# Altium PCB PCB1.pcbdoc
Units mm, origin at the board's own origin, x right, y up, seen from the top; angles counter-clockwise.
Board outline 70.36 x 65.79 mm, 2 copper layers (Top Layer, Bottom Layer), stack 1.58 mm thick; 58 components, 70 nets, 284 pads, 61 vias.
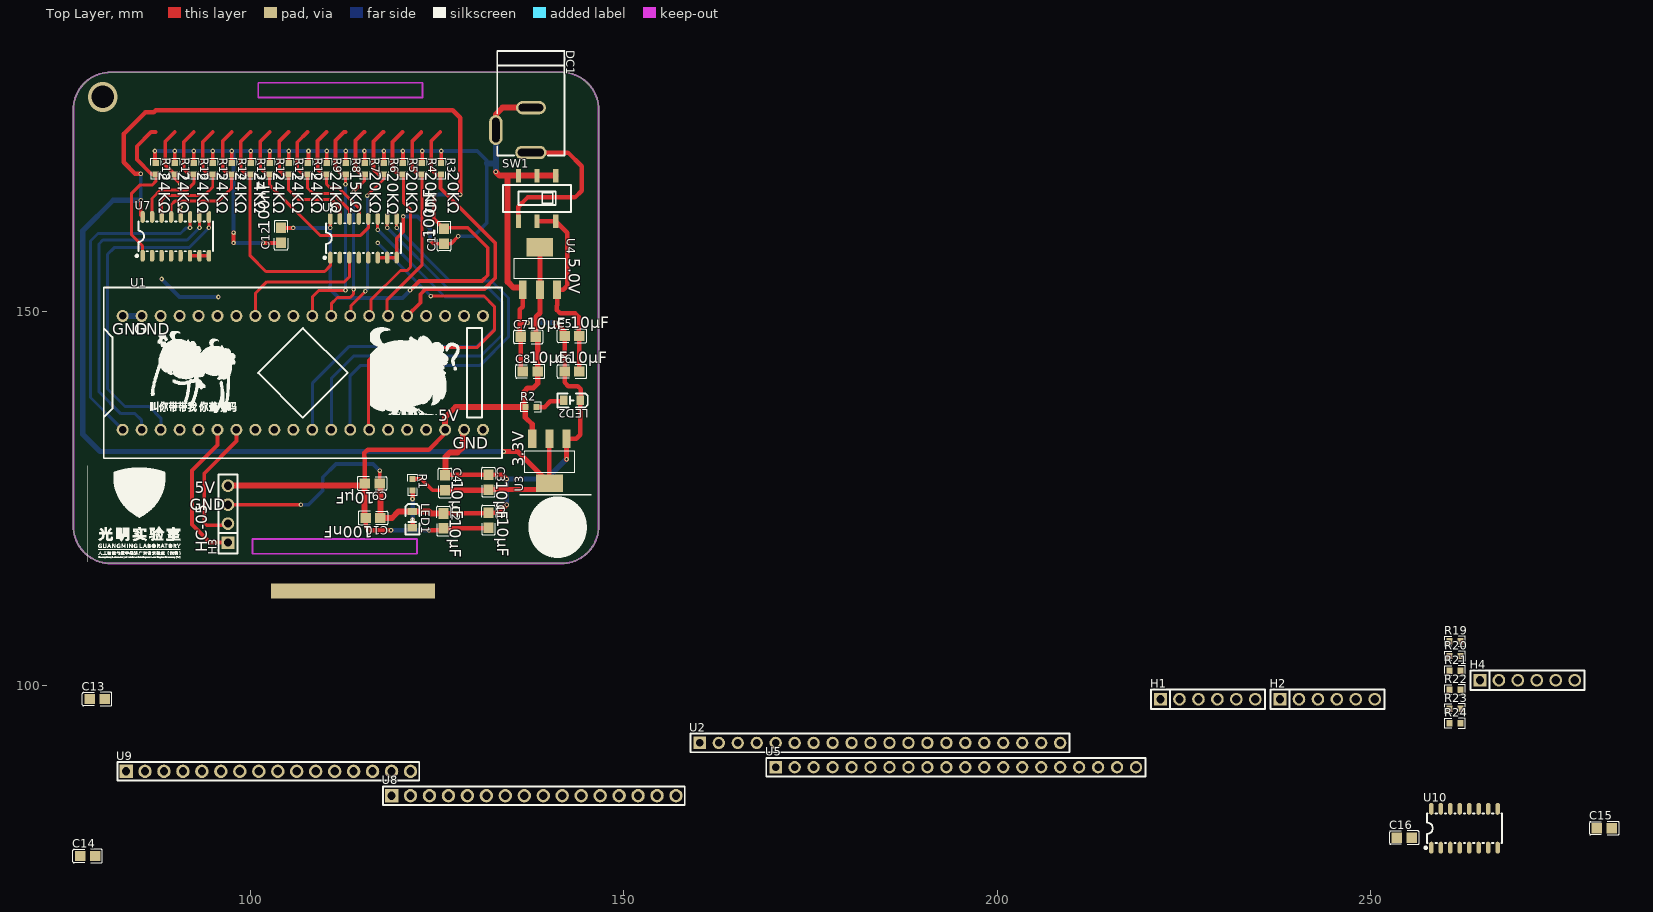
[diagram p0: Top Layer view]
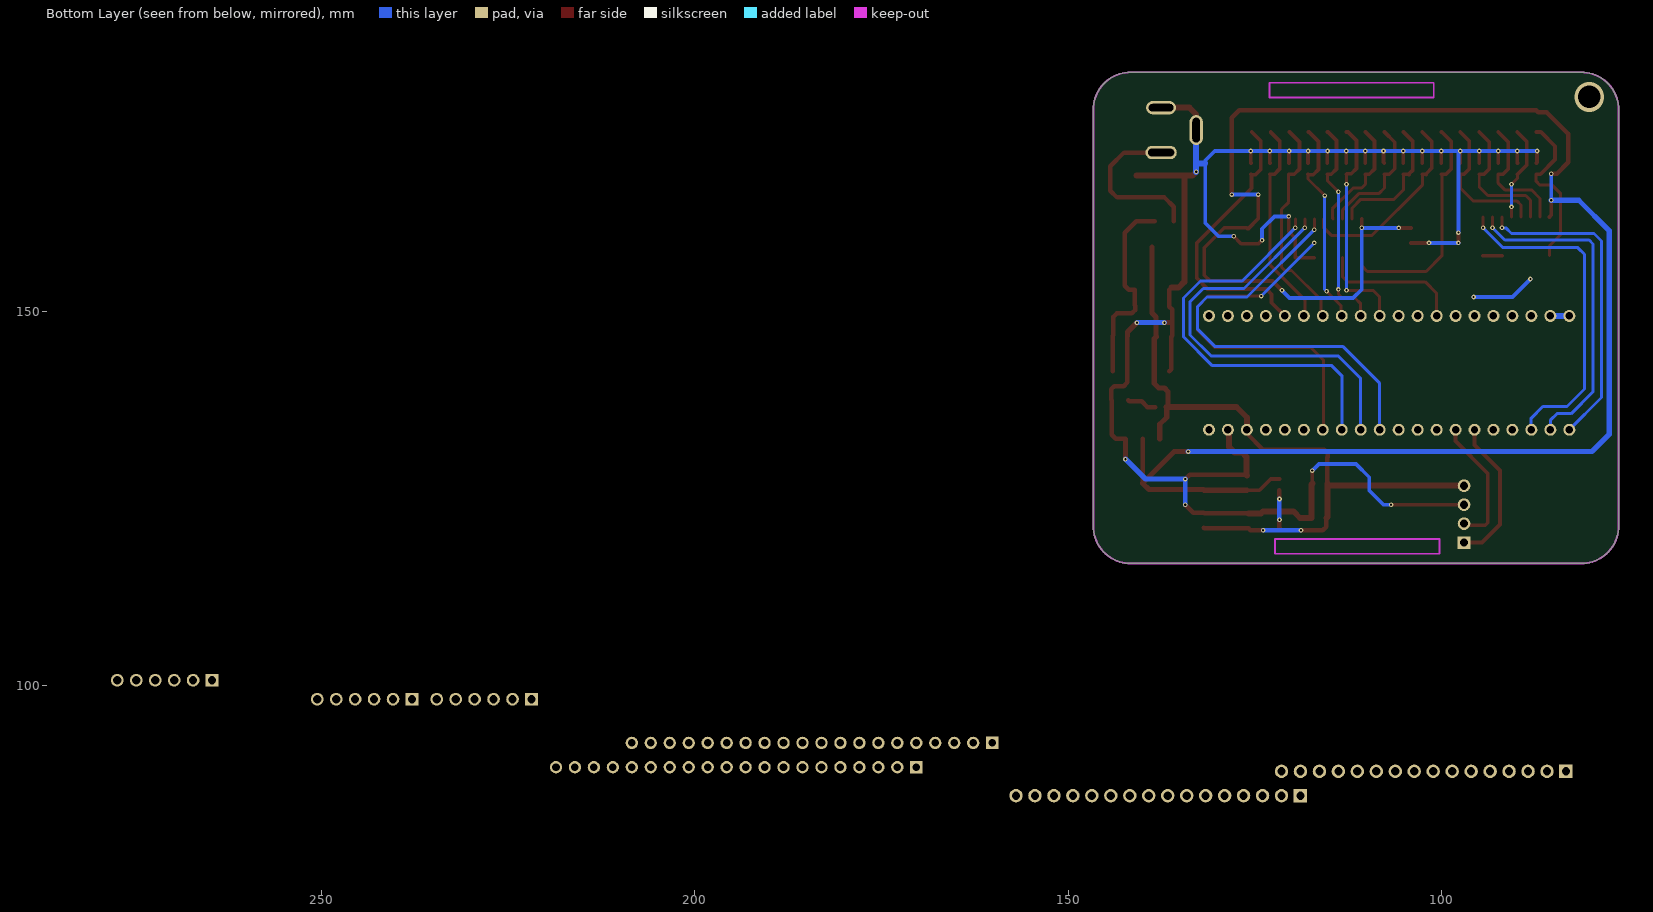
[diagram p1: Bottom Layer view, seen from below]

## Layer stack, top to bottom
Top Solder Mask Layer: solder mask 0.01, Dk 3.3
Top Layer: signal copper 0.035
Dielectric1: surface 1.51, FR4, Dk 4.5
Bottom Layer: signal copper 0.035
Bottom Solder Mask Layer: solder mask 0.01, Dk 3.3

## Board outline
81.251,182.084 ccw(c81.251,177.084) 76.251,177.084 76.251,121.298 ccw(c81.251,121.298) 81.251,116.298 141.609,116.298 ccw(c141.609,121.298) 146.609,121.298 146.609,177.084 ccw(c141.609,177.084) 141.609,182.084

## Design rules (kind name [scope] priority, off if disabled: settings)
BoardOutlineClearance copperThickness1oz [All] p0: genericclearance=0.254 ignorepadtopadclearanceinfootprint=FALSE except(0: Arc-SplitContinuation Track-SplitContinuation SMDPad-SplitContinuation THPad-SplitContinuation Via-SplitContinuation Fill-SplitContinuation Poly-SplitContinuation Region-SplitContinuation Text-SplitContinuation)
BoardOutlineClearance copperThickness2oz [All] p0: genericclearance=0.254 ignorepadtopadclearanceinfootprint=FALSE except(0: Arc-SplitContinuation Track-SplitContinuation SMDPad-SplitContinuation THPad-SplitContinuation Via-SplitContinuation Fill-SplitContinuation Poly-SplitContinuation Region-SplitContinuation Text-SplitContinuation)
BoardOutlineClearance Plane_innerPlane [All] p0: genericclearance=0.254 ignorepadtopadclearanceinfootprint=FALSE except(0: Arc-SplitContinuation Track-SplitContinuation SMDPad-SplitContinuation THPad-SplitContinuation Via-SplitContinuation Fill-SplitContinuation Poly-SplitContinuation Region-SplitContinuation Text-SplitContinuation)
BoardOutlineClearance Copper_copperRegion [All] p0: genericclearance=0.254 ignorepadtopadclearanceinfootprint=FALSE except(0: Arc-SplitContinuation Track-SplitContinuation SMDPad-SplitContinuation THPad-SplitContinuation Via-SplitContinuation Fill-SplitContinuation Poly-SplitContinuation Region-SplitContinuation Text-SplitContinuation)
BoardOutlineClearance otherClearance [All] p0: genericclearance=0.254 ignorepadtopadclearanceinfootprint=FALSE except(0: Arc-SplitContinuation Track-SplitContinuation SMDPad-SplitContinuation THPad-SplitContinuation Via-SplitContinuation Fill-SplitContinuation Poly-SplitContinuation Region-SplitContinuation Text-SplitContinuation)
Clearance copperThickness1oz [All] p1: gap=0.178 ignorepadtopadclearanceinfootprint=FALSE
Clearance copperThickness2oz [All] p1: gap=0.178 ignorepadtopadclearanceinfootprint=FALSE
Clearance Plane_innerPlane [All] p1: gap=0.178 ignorepadtopadclearanceinfootprint=FALSE
Clearance Copper_copperRegion [All] p1: gap=0.178 ignorepadtopadclearanceinfootprint=FALSE
Clearance otherClearance [All] p1: gap=0.178 ignorepadtopadclearanceinfootprint=FALSE
DiffPairsRouting differentialPair [All] p1: maxuncoupledlength=10 minlimit=6 maxlimit=Infinity mostfreqgap=6 toplayer_minwidth=5 toplayer_prefwidth=10 toplayer_maxwidth=100 bottomlayer_minwidth=5 bottomlayer_prefwidth=10 bottomlayer_maxwidth=100
PasteMaskExpansion pasteMaskExpansion [All] p1: expansion=0
PlaneConnect innerPlane [All] p1: planeconnectstyle=Relief reliefexpansion=0.508 reliefentries=4 reliefconductorwidth=0.254 reliefairgap=0.254
PolygonConnect copperRegion [All] p1: connectstyle=Relief reliefentries=4 reliefconductorwidth=10 polygonreliefangle="90 Angle" airgapwidth=10
RoutingVias viaSize [All] p1: viastyle="Through Hole" holewidth=12.0078 minholewidth=11.811 maxholewidth=248.0314 width=12.0078 minwidth=11.811 maxwidth=248.0314
SolderMaskExpansion solderMaskExpansion [IsVia] p1: useseparateexpansions=TRUE expansion=-1000 expansionbottom=-1000
SolderMaskExpansion solderMaskExpansion [All] p2: useseparateexpansions=TRUE expansion=2 expansionbottom=2
Width copperThickness1oz [All] p1: maxlimit=100 minlimit=5 preferedwidth=10
Width copperThickness2oz [All] p1: maxlimit=100 minlimit=8 preferedwidth=10

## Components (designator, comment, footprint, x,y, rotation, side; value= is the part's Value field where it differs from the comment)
C1 "10UF" C0805 131.845,122.108 r270 top
C2 "10UF" C0805 125.814,121.991 r270 top
C3 "10UF" C0805 131.845,127.192 r270 top
C4 "10UF" C0805 126.035,127.093 r270 top
C5 "10UF" C0805 143.034,146.785 r0 top
C6 "10UF" C0805 143.037,142.024 r0 top
C7 "10UF" C0805 137.188,146.658 r0 top
C8 "10UF" C0805 137.452,142.024 r0 top
C9 "100nF" C0805 116.261,127.013 r180 top
C10 "10μF" C0805 116.383,122.394 r180 top
C11 "10nF" C0805 125.908,160.113 r90 top
C12 "10nF" C0805 104.064,160.24 r90 top
C13 "10nF" C0805 79.434,98.121 r0 top
C14 "10nF" C0805 78.164,77.104 r0 top
C15 "100nF" C0805 281.305,80.833 r0 top
C16 "100nF" C0805 254.524,79.563 r0 top
DC1 "DC-005-5A-2.0" DC-IN-TH_DC-005-5A-2.0 135.179,174.337 r270 top
H1 "PZ254V-11-06P" HDR-TH_6P-P2.54-V-M 228.204,98.121 r0 top
H2 "PZ254V-11-06P" HDR-TH_6P-P2.54-V-M 244.208,98.121 r0 top
H3 "" HDR-TH_4P-P2.54-V-F 96.952,122.902 r90 top
H4 "PZ254V-11-06P" HDR-TH_6P-P2.54-V-M 270.988,100.661 r0 top
LED1 "" LED_0805 121.655,122.108 r270 top
LED2 "" LED_0805 142.998,138.141 r180 top
R1 "1K" R0603 121.677,126.849 r270 top
R2 "1K" R0603 137.537,137.252 r0 top
R3 "24K" R0603 125.489,169.178 r270 top
R4 "24K" R0603 122.94,169.178 r270 top
R5 "24K" R0603 120.392,169.178 r270 top
R6 "24K" R0603 117.843,169.178 r270 top
R7 "24K" R0603 115.295,169.178 r270 top
R8 "24K" R0603 112.747,169.178 r270 top
R9 "24K" R0603 110.198,169.178 r270 top
R10 "24K" R0603 107.65,169.178 r270 top
R11 "24K" R0603 105.101,169.178 r270 top
R12 "24K" R0603 102.553,169.178 r270 top
R13 "24K" R0603 100.005,169.178 r270 top
R14 "24K" R0603 97.456,169.178 r270 top
R15 "24K" R0603 94.908,169.178 r270 top
R16 "24K" R0603 92.359,169.178 r270 top
R17 "24K" R0603 89.811,169.178 r270 top
R18 "24K" R0603 87.263,169.178 r270 top
R19 "1K" R0603 261.3,105.878 r0 top
R20 "1K" R0603 261.3,103.904 r0 top
R21 "1K" R0603 261.3,101.931 r0 top
R22 "1K" R0603 261.3,99.391 r0 top
R23 "1K" R0603 261.3,96.851 r0 top
R24 "1K" R0603 261.3,94.877 r0 top
SW1 "SS-3235S-L1" SW-SMD_SS-3235S-LX 138.354,165.193 r0 top
U1 "LCKFB-DKX-STM32F103C8T6" CONN-TH_L53.3-W22.9_STM32F103C8T6-CARD 106.985,141.825 r0 top
U2 "KH-2.54FH-1X20P-H8.5" HDR-TH_20P-P2.54-V-F-2 184.29,92.263 r0 top
U3 "AMS1117-3.3" SOT-223-3_L6.5-W3.4-P2.30-LS7.0-BR 140.005,130.014 r90 top
U4 "AMS1117-5.0" SOT-223_L6.5-W3.5-P2.30-LS7.0-BR 138.735,155.795 r270 top
U5 "KH-2.54FH-1X20P-H8.5" HDR-TH_20P-P2.54-V-F-2 194.45,89.009 r0 top
U6 "CD4051BM/TR" SOP-16_L9.9-W3.9-P1.27-LS6.1-BL 115.113,159.859 r0 top
U7 "CD4051BM/TR" SOP-16_L9.9-W3.9-P1.27-LS6.1-BL 89.967,160.113 r0 top
U8 "ZX-PZ2.54-1-16PZZ" HDR-TH_16P-P2.54-V-M-2 137.916,85.199 r0 top
U9 "ZX-PZ2.54-1-16PZZ" HDR-TH_16P-P2.54-V-M-2 102.356,88.453 r0 top
U10 "CD4051BM/TR" SOP-16_L9.9-W3.9-P1.27-LS6.1-BL 262.57,80.833 r0 top

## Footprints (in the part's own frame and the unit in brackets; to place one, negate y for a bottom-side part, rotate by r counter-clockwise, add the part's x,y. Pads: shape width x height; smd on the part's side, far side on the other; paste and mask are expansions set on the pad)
C0805 [mm]
  rect 1.41x1.35 smd paste-100 mask+0.051: 1(-1,0) 2(1,0)
  silkscreen extent -1.96,-0.9 1.96,0.9
CONN-TH_L53.3-W22.9_STM32F103C8T6-CARD [mm]
  round 1.6 hole 1: 1(-24.13,-7.62) 2(-21.59,-7.62) 3(-19.05,-7.62) 4(-16.51,-7.62) 5(-13.97,-7.62) 6(-11.43,-7.62) 7(-8.89,-7.62) 8(-6.35,-7.62) 9(-3.81,-7.62) 10(-1.27,-7.62) 11(1.27,-7.62) 12(3.81,-7.62) 13(6.35,-7.62) 14(8.89,-7.62) 15(11.43,-7.62) 16(13.97,-7.62) 17(16.51,-7.62) 18(19.05,-7.62) 19(21.59,-7.62) 20(24.13,-7.62) 21(24.13,7.62) 22(21.59,7.62) 23(19.05,7.62) 24(16.51,7.62) 25(13.97,7.62) 26(11.43,7.62) 27(8.89,7.62) 28(6.35,7.62) 29(3.81,7.62) 30(1.27,7.62) 31(-1.27,7.62) 32(-3.81,7.62) 33(-6.35,7.62) 34(-8.89,7.62) 35(-11.43,7.62) 36(-13.97,7.62) 37(-16.51,7.62) 38(-19.05,7.62) 39(-21.59,7.62) 40(-24.13,7.62)
  silkscreen extent -26.67,-11.43 26.67,11.43
DC-IN-TH_DC-005-5A-2.0 [mm]
  oval 1.8x4.2 hole 1 slot 3.5 at 90 deg: 1(3,2.352)
  oval 1.8x4 hole 1 slot 3.3 at 90 deg: 2(-3,2.352)
  oval 4x1.8 hole 1 slot 3.3 at 0 deg: 3(0,-2.352)
  silkscreen extent -10.6,-2.15 3.4,6.85
HDR-TH_4P-P2.54-V-F [mm]
  rect 1.7x1.7 hole 1.1: 1(-3.81,0)
  round 1.7 hole 1.1: 2(-1.27,0) 3(1.27,0) 4(3.81,0)
  silkscreen extent -5.29,-1.27 5.29,1.27
HDR-TH_6P-P2.54-V-M [mm]
  rect 1.7x1.7 hole 1.1: 1(-6.35,0)
  round 1.7 hole 1.1: 2(-3.81,0) 3(-1.27,0) 4(1.27,0) 5(3.81,0) 6(6.35,0)
  silkscreen extent -7.6,-1.3 7.65,1.3
HDR-TH_16P-P2.54-V-M-2 [mm]
  rect 1.8x1.8 hole 1.1: 1(-19.05,0)
  round 1.8 hole 1.1: 2(-16.51,0) 3(-13.97,0) 4(-11.43,0) 5(-8.89,0) 6(-6.35,0) 7(-3.81,0) 8(-1.27,0) 9(1.27,0) 10(3.81,0) 11(6.35,0) 12(8.89,0) 13(11.43,0) 14(13.97,0) 15(16.51,0) 16(19.05,0)
  silkscreen extent -20.22,-1.25 20.22,1.25
HDR-TH_20P-P2.54-V-F-2 [mm]
  rect 1.65x1.65 hole 1.02: 1(-24.13,0)
  round 1.65 hole 1.02: 2(-21.59,0) 3(-19.05,0) 4(-16.51,0) 5(-13.97,0) 6(-11.43,0) 7(-8.89,0) 8(-6.35,0) 9(-3.81,0) 10(-1.27,0) 11(1.27,0) 12(3.81,0) 13(6.35,0) 14(8.89,0) 15(11.43,0) 16(13.97,0) 17(16.51,0) 18(19.05,0) 19(21.59,0) 20(24.13,0)
  silkscreen extent -25.4,-1.25 25.4,1.25
LED_0805 [mm]
  rect 1x1.25 smd paste+0 mask+0.051: 1(-1.15,0.005) 2(1.05,0.005)
  silkscreen extent -2.15,-0.94 1.93,0.97
R0603 [mm]
  rect 0.806x0.864 smd paste-100 mask+0.051: 1(-0.753,0) 2(0.753,0)
  silkscreen extent -1.39,-0.66 1.39,0.66
SOP-16_L9.9-W3.9-P1.27-LS6.1-BL [mm]
  oval 0.6x1.6 smd: 1(-4.445,-2.6) 2(-3.175,-2.6) 3(-1.905,-2.6) 4(-0.635,-2.6) 5(0.635,-2.6) 6(1.905,-2.6) 7(3.175,-2.6) 8(4.445,-2.6) 9(4.445,2.6) 10(3.175,2.6) 11(1.905,2.6) 12(0.635,2.6) 13(-0.635,2.6) 14(-1.905,2.6) 15(-3.175,2.6) 16(-4.445,2.6)
  silkscreen extent -5.36,-2.76 5,2
SOT-223-3_L6.5-W3.4-P2.30-LS7.0-BR [mm]
  rect 2.5x1.1 smd: 1(2.97,-2.3) 2(2.97,0) 3(2.97,2.3)
  rect 2.34x3.6 smd: 4(-2.97,0)
  silkscreen extent -1.57,-3.33 1.37,3.33
SOT-223_L6.5-W3.5-P2.30-LS7.0-BR [mm]
  rect 2.465x1.05 smd: 1(2.858,-2.3) 2(2.857,0) 3(2.857,2.3)
  rect 2.465x3.54 smd: 4(-2.857,0)
  silkscreen extent -1.4,-3.4 1.4,3.4
SW-SMD_SS-3235S-LX [mm]
  rect 0.7x1.8 smd: 1(-2.5,3.05) 2(0,3.05) 3(2.5,3.05) 4(-2.5,-3.05) 5(0,-3.05) 6(2.5,-3.05)
  silkscreen extent -4.55,-1.8 4.55,1.8

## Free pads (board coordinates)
  rect 22x2 smd: 2(113.716,112.615)

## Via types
v1: diameter 0.61, hole 0.305, Top Layer to Bottom Layer, 60 vias
v2: diameter 4, hole 3, Top Layer to Bottom Layer, 1 vias

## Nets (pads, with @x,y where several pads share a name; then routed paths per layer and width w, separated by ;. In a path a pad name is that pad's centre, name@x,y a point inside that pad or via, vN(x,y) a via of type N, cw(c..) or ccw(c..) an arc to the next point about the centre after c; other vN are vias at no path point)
$1N1602: LED2.2 R2.2 | length 4
  Top Layer w0.6: R2.2 139.369,137.252 140.132,138.015 141.827,138.015 LED2.2
$1N1617: LED1.2 R1.2 | length 5
  Top Layer w0.6: LED1.2 121.677,121.074 v1(121.677,122.14) ; v1(121.677,124.934) R1.2
  Bottom Layer w0.6: v1(121.677,122.14) v1(121.677,124.934)
$1N7376: H4.1 R19.2
$1N7377: H4.2 R20.2
$1N7378: H4.3 R21.2
$1N7379: H4.4 R22.2
$1N7380: H4.5 R23.2
$1N7381: H4.6 R24.2
$1N7401: U10.4
+3.3V: C3.2 C4.2 C11.2 C12.2 C15.2 H1.1 H1.2 H1.3 H1.4 H1.5 H1.6 R1.1 U3.2 U3.4 U6.16 U7.16 U9.1 U9.2 U9.3 U9.4 U9.5 U9.6 U9.7 U9.8 U9.9 U9.10 U9.11 U9.12 U9.13 U9.14 U9.15 U9.16 U10.16 | length 255.2
  Top Layer w0.5: v1(85.268,164.939) 85.268,162.967 U7.16 ; C12.2 v1(105.715,161.24) ; v1(110.668,161.256) U6.16 ; v1(121.336,152.874) 122.606,154.144 130.988,154.144 131.75,154.906 131.75,158.589 129.083,161.256 126.051,161.256 C11.2 124.511,162.51 v1(124.511,165.701) ; R1.1 122.858,127.602 124.368,126.093 C4.2
  Top Layer w0.6: v1(85.268,168.495) 84.506,168.495 82.982,170.019 82.982,173.829 85.903,176.75 87.046,176.75 87.3,177.004 127.051,177.004 128.067,175.988 v1(128.067,165.701) ; U3.4 U3.2
  Top Layer w0.7: C4.2 131.746,126.093 C3.2 139.153,126.192 U3.4 135.765,131.284 v1(133.909,131.284)
  Bottom Layer w0.5: v1(85.268,164.939) v1(85.268,168.495) ; v1(105.715,161.24) 110.652,161.24 v1(110.668,161.256) 110.668,153.001 111.811,151.858 120.32,151.858 v1(121.336,152.874) ; v1(124.511,165.701) v1(128.067,165.701)
  Bottom Layer w0.7: v1(85.268,164.939) 81.585,164.939 77.521,160.875 77.521,133.57 79.807,131.284 v1(133.909,131.284)
+5V: C1.2 C2.2 C7.2 C8.2 C9.2 C10.2 H3.4 R2.1 U2.18 U3.3 U4.2 U4.4 | length 98.2
  Top Layer w0.6: C9.2 115.261,130.501 115.24,130.522 115.24,131.122 115.664,131.546 123.876,131.546 126.035,133.705 126.035,134.205 ; C10.2 115.383,121.235 115.875,120.743 v1(118.796,120.743) ; v1(123.876,120.743) 125.566,120.743 C2.2 131.727,120.991 C1.2
  Top Layer w0.7: U3.3 137.705,134.935 136.784,135.856 R2.1 136.589,137.447 136.589,139.298 137.084,139.793 137.846,139.793 138.452,140.399 C8.2 138.452,146.394 C7.2 138.227,146.696 138.227,149.318 138.735,149.826 U4.2 U4.4
  Top Layer w0.8: H3.4 114.959,126.712 C9.2 115.261,122.516 C10.2 ; 126.035,134.205 126.035,135.856 127.431,137.252 R2.1
  Bottom Layer w0.6: v1(118.796,120.743) v1(123.876,120.743)
+9V: C5.2 C6.2 SW1.5 SW1.6 U4.3 | length 26.7
  Top Layer w0.6: SW1.5 SW1.6 142.418,160.579 142.418,153.509 141.846,152.937 U4.3 141.035,150.856 141.021,150.842 141.021,150.242 141.445,149.817 143.442,149.817 143.942,149.318 143.942,146.876 C5.2 144.037,146.781 C6.2
+9V-BATTERY: DC1.1 SW1.4 | length 22.1
  Top Layer w0.6: SW1.4 135.854,164.09 137.084,165.32 143.434,165.32 144.323,166.209 144.323,169.511 142.497,171.337 DC1.1
GND: C1.1 C2.1 C3.1 C4.1 C5.1 C6.1 C7.1 C8.1 C9.1 C10.1 C11.1 C12.1 C13.1 C14.1 C15.1 C16.1 DC1.2 DC1.3 H2.1 H2.2 H2.3 H2.4 H2.5 H2.6 H3.3 LED1.1 LED2.1 R3.1 R4.1 R5.1 R6.1 R7.1 R8.1 R9.1 R10.1 R11.1 R12.1 R13.1 R14.1 R15.1 R16.1 R17.1 R18.1 SW1.1 SW1.2 SW1.3 U2.19 U3.1 U4.1 U5.1 U5.2 U6.6 U6.7 U6.8 U7.6 U7.7 U7.8 U10.6 U10.7 U10.8 | length 279.7
  Top Layer w0.5: v1(87.173,171.543) 87.173,170.021 R18.1 ; R17.1 89.84,169.96 v1(89.84,171.543) ; U7.6 U7.7 U7.8 ; R16.1 v1(92.359,171.543) ; R15.1 v1(94.908,171.543) ; H3.3 v1(106.731,124.172) ; R14.1 97.46,169.935 v1(97.46,171.543) ; v1(97.714,159.224) v1(97.714,160.621) ; R13.1 v1(100.005,171.543) ; v1(101.651,159.224) 104.048,159.224 C12.1 ; R12.1 v1(102.553,171.543) ; R11.1 v1(105.101,171.543) ; R10.1 107.747,170.028 v1(107.747,171.543) ; R9.1 v1(110.198,171.543) ; R8.1 v1(112.747,171.543) ; v1(115.24,171.543) 115.295,171.487 R7.1 ; U6.6 U6.7 U6.8 119.558,159.859 120.447,160.748 v1(120.447,162.78) ; C9.1 117.272,127.024 v1(117.272,128.744) ; R6.1 v1(117.843,171.543) ; R5.1 v1(120.392,171.543) ; R4.1 122.987,169.978 v1(122.987,171.543) ; v1(124.003,159.605) 124.495,159.113 C11.1 126.813,159.113 v1(127.813,160.113) ; R3.1 125.527,169.97 v1(125.527,171.543)
  Top Layer w0.6: C2.1 131.727,122.991 C1.1 133.227,123.108 v1(134.29,124.172) ; C4.1@126.134,128.192 C3.1 133.699,128.192 v1(134.29,127.601) ; U4.1 136.435,150.701 136.068,150.334 136.068,148.589 136.068,146.778 C7.1 136.188,142.288 C8.1 ; C5.1 142.037,146.781 C6.1 142.037,140.555 142.545,140.047 143.815,140.047 144.239,139.622 144.239,138.226 LED2.1 144.148,133.522 143.61,132.984 U3.1
  Top Layer w0.7: 136.068,148.589 136.101,148.556 v1(137.084,148.556) ; v1(140.767,148.556) 142.034,147.289 C5.1 ; v1(142.305,130.268) U3.1
  Top Layer w0.8: C9.1 117.383,126.891 C10.1 118.923,122.394 119.788,123.259 LED1.1 123.9,123.259 124.168,122.991 C2.1 ; C4.1 126.104,128.162 126.104,130.591 126.67,131.157 127.686,131.157 128.448,131.919 128.448,134.078 128.575,134.205 ; v1(132.827,168.749) 133.333,168.243 134.41,168.243 ; DC1.3 132.827,176.43 133.734,177.337 DC1.2 ; U4.1@136.117,153.255 135.179,153.255 134.41,154.023 134.41,168.243 ; SW1.3 SW1.2 SW1.1 134.41,168.243
  Bottom Layer w0.5: v1(87.173,171.543) v1(89.84,171.543) v1(92.359,171.543) v1(94.908,171.543) v1(97.46,171.543) ; v1(97.714,159.224) v1(101.651,159.224) ; v1(97.714,160.621) 97.714,171.289 v1(97.46,171.543) ; v1(106.731,124.172) 107.747,124.172 109.652,126.077 109.652,127.855 111.43,129.633 116.383,129.633 v1(117.272,128.744) ; v1(120.447,162.78) 122.352,162.78 124.003,161.129 v1(124.003,159.605) ; v1(127.813,160.113) 129.845,160.113 131.623,161.891 131.623,169.94 131.623,170.273 130.353,171.543 v1(125.527,171.543) v1(122.987,171.543) v1(120.392,171.543) v1(117.843,171.543) v1(115.24,171.543) v1(112.747,171.543) v1(110.198,171.543) v1(107.747,171.543) v1(105.101,171.543) v1(102.553,171.543) v1(100.005,171.543) v1(97.46,171.543)
  Bottom Layer w0.6: v1(134.29,124.172) v1(134.29,127.601)
  Bottom Layer w0.7: v1(134.29,127.601) 139.638,127.601 v1(142.305,130.268) ; v1(137.084,148.556) v1(140.767,148.556)
  Bottom Layer w0.8: 82.855,149.445 85.395,149.445 ; 131.623,169.94 131.671,169.892 132.827,169.892 ; v1(132.827,168.749) 132.827,169.892 ; DC1.3 132.827,169.892
H0: R3.2 U6.13 U8.1 | length 15.5
  Top Layer w0.4: 110.198,168.425 110.198,168.298 110.16,168.259 110.16,167.098 110.668,166.59 111.811,166.59 114.605,163.796 114.605,162.586 U6.13
  Top Layer w0.5: 110.16,174.083 108.956,172.879 108.956,169.121 109.652,168.425 110.198,168.425
H1: R4.2 U6.14 U8.2 | length 17
  Top Layer w0.4: 107.65,168.425 107.62,168.395 107.62,166.59 108.382,165.828 111.049,165.828 113.208,163.669 U6.14
  Top Layer w0.5: 107.62,174.083 106.251,172.714 106.251,169.158 106.985,168.425 107.65,168.425
H2: R5.2 U6.15 U8.3 | length 18.7
  Top Layer w0.4: 105.101,168.425 105.08,168.403 105.08,166.336 106.35,165.066 110.795,165.066 111.938,163.923 U6.15
  Top Layer w0.5: 105.08,174.083 103.81,172.813 103.81,169.003 104.318,168.495 104.318,168.368 104.375,168.425 105.101,168.425
H3: R6.2 U6.12 U8.4 U10.12 | length 26.2
  Top Layer w0.4: 102.553,168.425 102.54,168.412 102.54,166.971 109.271,160.24 114.732,160.24 115.748,161.256 U6.12
  Top Layer w0.5: 102.54,174.083 101.27,172.813 101.27,169.257 102.032,168.495 102.032,168.368 102.089,168.425 102.553,168.425
H4: R7.2 U6.1 U8.5 | length 31.1
  Top Layer w0.4: 100.005,168.425 99.936,168.356 99.936,157.509 102.032,155.414 109.906,155.414 110.668,156.176 U6.1
  Top Layer w0.5: 100,174.083 99.939,174.083 98.669,172.813 98.669,169.121 99.365,168.425 100.005,168.425
H5: R8.2 U6.5 U8.6
H6: R9.2 U6.2 U8.7
H7: R10.2 U6.4 U8.8
H8: R11.2 U7.13 U8.9 | length 19.5
  Top Layer w0.4: U7.13 89.332,164.304 89.84,164.812 95.682,164.812 97.46,166.59 97.46,168.421 97.456,168.425
  Top Layer w0.5: 97.456,168.425 96.952,168.425 96.256,169.121 96.256,172.879 97.46,174.083
H9: R12.2 U7.14 U8.10 | length 18.7
  Top Layer w0.4: U7.14 88.062,164.939 88.697,165.574 93.777,165.574 94.92,166.717 94.92,168.413 94.908,168.425
  Top Layer w0.5: 94.908,168.425 94.285,168.425 93.589,169.121 93.589,172.752 94.92,174.083
H10: R13.2 U7.15 U8.11 | length 17.2
  Top Layer w0.4: U7.15 86.792,165.193 87.935,166.336 91.491,166.336 92.38,167.225 92.38,168.404 92.359,168.425
  Top Layer w0.5: 92.359,168.425 91.745,168.425 91.049,169.121 91.049,172.752 92.38,174.083
H11: R14.2 U7.12 U8.12 | length 12.7
  Top Layer w0.4: 89.811,168.425 89.811,167.888 v1(90.602,167.098) ; U7.12 v1(90.602,164.05)
  Top Layer w0.5: 89.811,168.425 88.57,169.666 88.57,172.813 89.84,174.083
  Bottom Layer w0.4: v1(90.602,164.05) v1(90.602,167.098)
H12: R15.2 U7.1 U8.13 | length 22.3
  Top Layer w0.4: U7.1 85.522,158.843 84.061,160.303 84.061,165.891 85.141,166.971 86.792,166.971 87.3,167.479 87.3,168.388 87.263,168.425
  Top Layer w0.5: 87.263,168.425 86.735,168.425 84.76,170.4 84.76,172.178 86.665,174.083 87.3,174.083
H13: R16.2 U7.5 U8.14
H14: R17.2 U7.2 U8.15
H15: R18.2 U7.4 U8.16
HZ0: R19.1 U10.13
HZ1: R20.1 U10.14
HZ2: R21.1 U10.15
HZ3: R22.1
HZ4: R23.1 U10.1
HZ5: R24.1 U10.5
HZ6: U10.2
PA0: C16.2 U5.16 U10.3 | length 38.6
  Top Layer w0.5: 120.955,149.445 122.733,151.223 122.733,152.366 123.429,153.062 131.303,153.062 132.766,154.525 132.766,159.224 125.431,166.558 125.431,168.368 ; 125.4,174.083 124.196,172.879 124.196,169.064 124.892,168.368 125.431,168.368 ; 125.489,168.425 125.431,168.368
PA1: U5.15 U10.11 | length 28
  Top Layer w0.4: 118.415,149.445 118.288,149.572 118.288,151.604 122.923,156.239 122.923,168.408 122.94,168.425
  Top Layer w0.5: 122.86,174.083 121.656,172.879 121.656,169.121 122.352,168.425 122.94,168.425
PA2: U5.14 U10.10 | length 29.5
  Top Layer w0.4: 115.875,149.445 116.002,149.445 116.129,149.572 116.129,151.604 120.066,155.541 120.955,155.541 121.4,155.986 121.4,163.731 120.447,164.685 120.447,168.37 120.392,168.425
  Top Layer w0.5: 120.32,174.083 118.989,172.752 118.989,169.121 119.685,168.425 120.392,168.425
PA3: U5.13 U10.9 | length 28.2
  Top Layer w0.4: 113.335,149.445 113.462,149.572 113.462,150.842 v1(115.367,152.747) ; v1(115.621,165.574) 117.843,167.796 117.843,168.425
  Top Layer w0.5: 117.78,174.083 117.719,174.083 116.449,172.813 116.449,169.064 117.145,168.368 117.786,168.368 117.843,168.425
  Bottom Layer w0.4: v1(115.367,152.747) 115.621,153.001 v1(115.621,165.574)
PA4: U5.12 | length 28.9
  Top Layer w0.4: 110.795,149.445 110.795,151.096 111.62,151.921 113.335,151.921 113.78,152.367 v1(113.78,153.001) ; v1(113.78,166.082) 115.24,167.541 115.24,168.37 115.295,168.425
  Top Layer w0.5: 115.24,174.083 115.179,174.083 114.036,172.94 114.036,169.121 114.732,168.425 115.295,168.425
  Bottom Layer w0.4: v1(113.78,153.001) v1(113.78,166.082)
PA5: U5.11 U6.11 U7.11 | length 30.2
  Top Layer w0.4: 108.255,149.445 108.255,151.985 109.144,152.874 v1(112.7,152.874) ; v1(112.7,167.098) 112.7,168.378 112.747,168.425
  Top Layer w0.5: 112.7,174.083 112.512,174.083 111.369,172.94 111.369,169.191 112.065,168.495 112.677,168.495 112.747,168.425
  Bottom Layer w0.4: v1(112.7,152.874) v1(112.7,167.098)
PA6: U5.10 U6.10 U7.10
PA7: U5.9 U6.9 U7.9
PA8: U2.5
PA9: H3.1 U2.6 | length 19.9
  Top Layer w0.5: 95.555,134.205 95.555,132.173 92.126,128.744 92.126,121.505 94.539,119.092 H3.1
PA10: H3.2 U2.7 | length 17.6
  Top Layer w0.5: H3.2 96.725,121.405 94.13,121.405 93.777,121.759 93.777,128.363 98.095,132.681 98.095,134.205
PA11: U2.8
PA12: U2.9
PA15: U2.10
PB0: C13.2 U5.8 U6.3 | length 19.1
  Top Layer w0.4: 100.635,149.445 100.635,152.493 102.159,154.017 112.573,154.017 113.208,154.652 U6.3
PB1: C14.2 U5.7 U7.3 | length 8.6
  Bottom Layer w0.5: v1(88.062,154.398) 90.475,151.985 v1(95.682,151.985)
PB3: U2.11 | length 58
  Top Layer w0.4: v1(117.018,161.002) 117.018,162.459
  Bottom Layer w0.4: 108.255,134.205 108.255,140.428 113.208,145.381 130.353,145.381 132.639,147.667 132.639,150.715 131.369,151.985 126.035,151.985 v1(117.018,161.002)
PB4: U2.12 | length 57.3
  Top Layer w0.4: v1(118.288,161.256) 118.288,162.459
  Bottom Layer w0.4: 110.795,134.205 110.795,141.063 113.843,144.111 130.861,144.111 133.655,146.905 133.655,151.35 131.877,153.128 126.416,153.128 v1(118.288,161.256)
PB5: U2.13 | length 55.9
  Top Layer w0.4: v1(119.558,161.256) 119.558,162.459
  Bottom Layer w0.4: 113.335,134.205 113.335,141.444 114.732,142.841 130.734,142.841 134.544,146.651 134.544,151.858 132.258,154.144 126.67,154.144 v1(119.558,161.256)
PB6: U2.14 | length 50.2
  Top Layer w0.4: 115.875,134.205 115.748,134.332 115.748,143.476 117.526,145.254 130.353,145.254 132.639,147.54 132.639,150.715 131.242,152.112 v1(124.13,152.112)
  Bottom Layer w0.4: v1(117.018,159.224) v1(124.13,152.112)
PB7: U2.15
PB8: U2.16
PB9: U2.17
PB10: U5.6
PB11: U5.5
PB12: U2.1 | length 42.6
  Top Layer w0.4: v1(91.872,161.256) 91.872,162.713
  Bottom Layer w0.4: 82.855,134.205 78.537,138.523 78.537,159.478 79.553,160.494 90.602,160.494 91.364,161.256 v1(91.872,161.256)
PB13: U2.2 | length 44.2
  Top Layer w0.4: v1(93.142,161.256) 93.142,162.713
  Bottom Layer w0.4: 85.395,134.205 85.395,135.475 84.506,136.364 82.601,136.364 79.68,139.285 79.68,159.097 80.188,159.605 91.491,159.605 v1(93.142,161.256)
PB14: U2.3 | length 44.9
  Top Layer w0.4: v1(94.412,161.256) 94.412,162.713
  Bottom Layer w0.4: 87.935,134.205 87.967,134.236 87.967,135.76 86.411,137.316 83.172,137.316 80.823,139.666 80.823,157.7 81.712,158.589 91.745,158.589 v1(94.412,161.256)
PB15: U2.4
PC13: U5.19
PC14: U5.18
PC15: U5.17
RESET: U5.4
pads on no net: U1.1 U1.2 U1.3 U1.4 U1.5 U1.6 U1.7 U1.8 U1.9 U1.10 U1.11 U1.12 U1.13 U1.14 U1.15 U1.16 U1.17 U1.18 U1.19 U1.20 U1.21 U1.22 U1.23 U1.24 U1.25 U1.26 U1.27 U1.28 U1.29 U1.30 U1.31 U1.32 U1.33 U1.34 U1.35 U1.36 U1.37 U1.38 U1.39 U1.40 U2.20 U5.3 U5.20
copper on no net:
  other v2: 80.188,178.782

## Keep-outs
Board Outline Layer:
  lines w0.254: 141.609,116.298 81.251,116.298 cw(c81.251,121.298) 76.251,121.298 76.251,177.084 cw(c81.251,177.084) 81.251,182.084 141.609,182.084 ; 141.609,116.298 141.609,116.298 ; 141.609,116.298 ccw(c141.609,121.298) 146.609,121.298 146.609,177.084 ccw(c141.609,177.084) 141.609,182.084 ; 141.609,182.084 141.609,182.084 ; 100.254,117.6 100.254,119.6 122.254,119.6 122.254,117.6 100.254,117.6 ; 101.016,178.687 101.016,180.687 123.016,180.687 123.016,178.687 101.016,178.687

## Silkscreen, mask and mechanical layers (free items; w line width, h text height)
Top Silkscreen Layer:
  drawing of 252 lines, arcs and shapes, not listed
  text "15KΩ" at 113.347,168.854 h1.5 r270
  text "24KΩ" at 97.906,168.783 h1.5 r270
  text "24KΩ" at 87.713,168.752 h1.5 r270
  text "24KΩ" at 90.234,168.752 h1.5 r270
  text "24KΩ" at 92.843,168.752 h1.5 r270
  text "24KΩ" at 95.428,168.749 h1.5 r270
  text "24KΩ" at 100.447,168.752 h1.5 r270
  text "24KΩ" at 103.048,168.749 h1.5 r270
  text "24KΩ" at 105.551,168.752 h1.5 r270
  text "24KΩ" at 108.118,168.752 h1.5 r270
  text "24KΩ" at 110.66,168.752 h1.5 r270
  text "20KΩ" at 115.956,168.752 h1.5 r270
  text "20KΩ" at 120.85,168.752 h1.5 r270
  text "20KΩ" at 123.39,168.752 h1.5 r270
  text "20KΩ" at 126.416,168.749 h1.5 r270
  text "20KΩ" at 118.288,168.622 h1.5 r270
  text "100nF" at 102.54,161.002 h1.5 r90
  text "100nF" at 124.623,159.859 h1.5 r90
  text "5.0V" at 142.617,157.191 h1.5 r270
  text "10μF" at 142.799,147.794 h1.5
  text "10μF" at 136.957,147.667 h1.5
  text "GND" at 81.458,146.905 h1.5
  text "GND" at 84.379,146.905 h1.5
  text "10μF" at 137.211,143.095 h1.5
  text "10μF" at 142.545,143.095 h1.5
  text "5V" at 125.146,135.348 h1.5
  text "GND" at 127.051,131.665 h1.5
  text "3.3V" at 136.576,129.252 h1.5 r90
  text "10μF" at 126.924,127.474 h1.5 r270
  text "10μF" at 132.893,127.347 h1.5 r270
  text "10μF" at 116.637,125.823 h1.5 r180
  text "5V" at 92.507,125.696 h1.5
  text "GND" at 91.872,123.41 h1.5
  text "10μF" at 133.02,122.394 h1.5 r270
  text "10μF" at 126.67,122.267 h1.5 r270
  text "100nF" at 116.383,121.251 h1.5 r180
  text "HC-05" at 94.158,117.822 h1.5 r90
